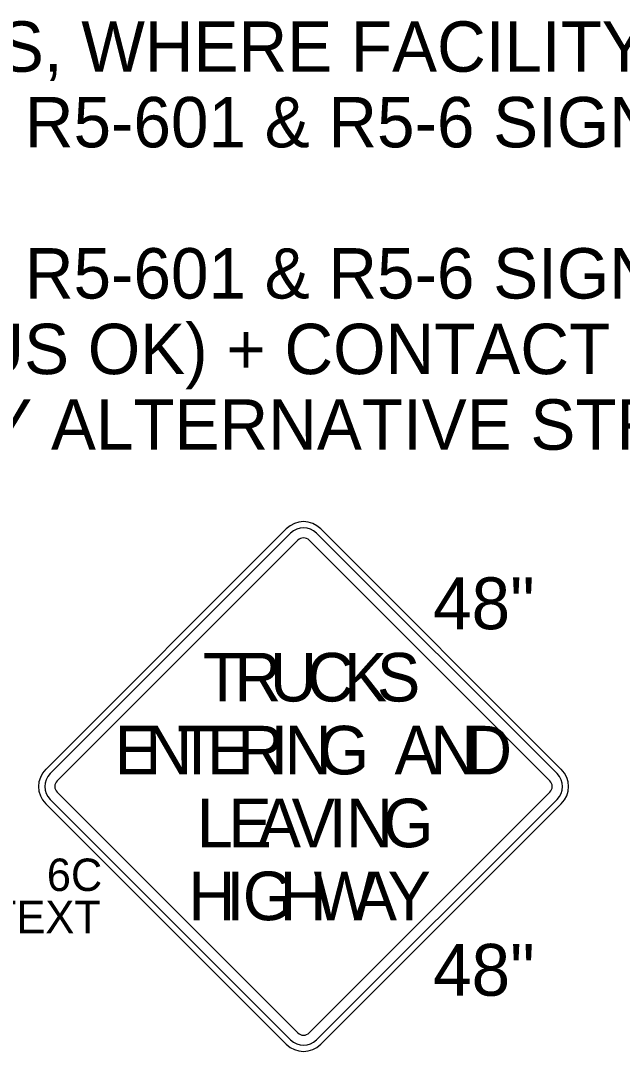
# Model space of a CAD drawing. Extents: x 99999 to 100116, y 99995 to 100013.
# Drawn here: x 100033.098 to 100033.934, y 100001.285 to 100002.717 of the extents above; entities that cross this region are included whole.
import ezdxf

# ---------------------------------------------------------------- set-up
doc = ezdxf.new("R2010")
doc.units = 0
doc.layers.add('SH_GI_GeneralNotesBodyText', color=7, linetype='Continuous')
doc.layers.add('TR_SN_ConstructionSigns', color=7, linetype='Continuous')

msp = doc.modelspace()

# ---------------------------------------------------------------- linework, layer by layer
at = {"layer": 'TR_SN_ConstructionSigns'}
for p, q in [((100033.4669, 100002.0107), (100033.1328, 100001.6766)), ((100033.8487, 100001.6766), (100033.5146, 100002.0107)), ((100033.4729, 100002.0048), (100033.1387, 100001.6707)), ((100033.1487, 100001.6607), (100033.4828, 100001.9948)), ((100033.4987, 100001.9948), (100033.8328, 100001.6607)), ((100033.8428, 100001.6707), (100033.5087, 100002.0048)), ((100033.1387, 100001.6349), (100033.4729, 100001.3008)), ((100033.4828, 100001.3107), (100033.1487, 100001.6448)), ((100033.8328, 100001.6448), (100033.4987, 100001.3107)), ((100033.5087, 100001.3008), (100033.8428, 100001.6349)), ((100033.1328, 100001.6289), (100033.4669, 100001.2948)), ((100033.5146, 100001.2948), (100033.8487, 100001.6289))]:
    msp.add_line(p, q, dxfattribs=at)
for centre, radius, start, end in [((100033.4908, 100001.9869), 0.0338, 45, 135), ((100033.4908, 100001.9869), 0.0253, 45, 135), ((100033.4908, 100001.9869), 0.0113, 45, 135), ((100033.1566, 100001.6528), 0.0338, 135, 225), ((100033.1566, 100001.6528), 0.0253, 135, 225), ((100033.8249, 100001.6528), 0.0253, 315, 45), ((100033.8249, 100001.6528), 0.0338, 315, 45), ((100033.1566, 100001.6528), 0.0113, 135, 225), ((100033.8249, 100001.6528), 0.0113, 315, 45), ((100033.4908, 100001.3187), 0.0113, 225, 315), ((100033.4908, 100001.3187), 0.0338, 225, 315), ((100033.4908, 100001.3187), 0.0253, 225, 315)]:
    msp.add_arc(centre, radius, start, end, dxfattribs=at)

# ---------------------------------------------------------------- texts
at = {"layer": 'SH_GI_GeneralNotesBodyText'}
for s, p in [('11. BICYCLIST ACCOMMODATIONS, WHERE FACILITY OPEN TO BICYCLES:', (100031.549, 100002.6456)), ('(A) BICYCLES PROHIBITED VIA R5-601 & R5-6 SIGNS. PROVIDE SIGNED DETOUR ', (100031.689, 100002.5406)), ('(B) BICYCLES PROHIBITED VIA R5-601 & R5-6 SIGNS. PROVIDE FREE SHUTTLE ', (100031.689, 100002.3306)), ('(WORK TRUCK, VAN, OR BUS OK) + CONTACT INFORMATION OR PHONE BOX.', (100031.839, 100002.2256)), ('(C) ENGINEER TO ACCEPT ANY ALTERNATIVE STRATEGIES.', (100031.689, 100002.1206))]:
    msp.add_text(s, height=0.07, rotation=360, dxfattribs=at).set_placement(p)
at = {"layer": 'TR_SN_ConstructionSigns'}
for p in [(100033.6706, 100001.8713), (100033.6706, 100001.3622)]:
    msp.add_text('48"', height=0.072, rotation=360, dxfattribs=at).set_placement(p)
for s, height, p in [('T', 0.0675, (100033.351, 100001.7709)), ('R', 0.0675, (100033.3949, 100001.7709)), ('U', 0.0675, (100033.4442, 100001.7709)), ('C', 0.0675, (100033.4955, 100001.7709)), ('K', 0.0675, (100033.5468, 100001.7709)), ('S', 0.0675, (100033.5927, 100001.7709)), ('E', 0.0675, (100033.2286, 100001.6696)), ('N', 0.0675, (100033.271, 100001.6696)), ('T', 0.0675, (100033.3154, 100001.6696)), ('E', 0.0675, (100033.3565, 100001.6696)), ('R', 0.0675, (100033.3989, 100001.6696)), ('I', 0.0675, (100033.4448, 100001.6696)), ('N', 0.0675, (100033.4646, 100001.6696)), ('G', 0.0675, (100033.5118, 100001.6696)), ('A', 0.0675, (100033.6171, 100001.6696)), ('N', 0.0675, (100033.667, 100001.6696)), ('D', 0.0675, (100033.7152, 100001.6696)), ('L', 0.0675, (100033.3426, 100001.5684)), ('E', 0.0675, (100033.3865, 100001.5684)), ('A', 0.0675, (100033.427, 100001.5684)), ('V', 0.0675, (100033.4742, 100001.5684)), ('I', 0.0675, (100033.5255, 100001.5684)), ('N', 0.0675, (100033.5498, 100001.5684)), ('G', 0.0675, (100033.6011, 100001.5684)), ('6C', 0.045, (100033.1343, 100001.5077)), ('H', 0.0675, (100033.3308, 100001.4671)), ('I', 0.0675, (100033.3834, 100001.4671)), ('G', 0.0675, (100033.4064, 100001.4671)), ('H', 0.0675, (100033.4577, 100001.4671)), ('W', 0.0675, (100033.5049, 100001.4671)), ('A', 0.0675, (100033.5603, 100001.4671)), ('Y', 0.0675, (100033.6075, 100001.4671)), ('TEXT', 0.045, (100033.0554, 100001.4491))]:
    msp.add_text(s, height=height, dxfattribs=at).set_placement(p)

doc.saveas('drawing.dxf')
